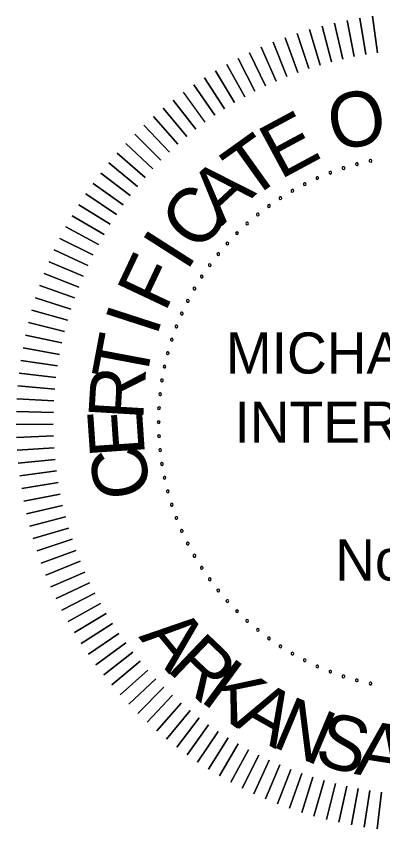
# Model space of a CAD drawing. Extents: x -4306 to 3843, y 131 to 8341.
# Drawn here: x 2723.6 to 2834.9, y 323.4 to 570.4 of the extents above; entities that cross this region are included whole.
import ezdxf

# ---------------------------------------------------------------- set-up
doc = ezdxf.new("R2010")
doc.units = 0
doc.layers.add('47', color=7, linetype='Continuous')

msp = doc.modelspace()

# ---------------------------------------------------------------- linework, layer by layer
at = {"layer": '47'}
for points in [[(2822.74, 557.35), (2820.23, 568.28)], [(2820.23, 568.28), (2822.74, 557.35)], [(2826.22, 558.09), (2824.06, 569.1)], [(2824.06, 569.1), (2826.22, 558.09)], [(2829.72, 558.72), (2827.9, 569.79)], [(2827.9, 569.79), (2829.72, 558.72)], [(2833.24, 559.24), (2831.77, 570.36)], [(2831.77, 570.36), (2833.24, 559.24)], [(2815.86, 555.54), (2812.67, 566.3)], [(2812.67, 566.3), (2815.86, 555.54)], [(2819.29, 556.5), (2816.44, 567.35)], [(2816.44, 567.35), (2819.29, 556.5)], [(2809.11, 553.3), (2805.25, 563.84)], [(2805.25, 563.84), (2809.11, 553.3)], [(2812.47, 554.47), (2808.94, 565.13)], [(2808.94, 565.13), (2812.47, 554.47)], [(2802.51, 550.65), (2798, 560.92)], [(2798, 560.92), (2802.51, 550.65)], [(2805.79, 552.03), (2801.6, 562.44)], [(2801.6, 562.44), (2805.79, 552.03)], [(2799.28, 549.17), (2794.44, 559.29)], [(2794.44, 559.29), (2799.28, 549.17)], [(2792.96, 545.9), (2787.5, 555.71)], [(2787.5, 555.71), (2792.96, 545.9)], [(2796.09, 547.58), (2790.94, 557.55)], [(2790.94, 557.55), (2796.09, 547.58)], [(2789.88, 544.12), (2784.11, 553.75)], [(2784.11, 553.75), (2789.88, 544.12)], [(2786.86, 542.25), (2780.79, 551.69)], [(2780.79, 551.69), (2786.86, 542.25)], [(2783.9, 540.28), (2777.54, 549.52)], [(2777.54, 549.52), (2783.9, 540.28)], [(2781, 538.22), (2774.35, 547.26)], [(2778.17, 536.07), (2771.24, 544.89)], [(2771.24, 544.89), (2778.17, 536.07)], [(2775.4, 533.83), (2768.2, 542.43)], [(2768.2, 542.43), (2775.4, 533.83)], [(2772.71, 531.5), (2765.24, 539.88)], [(2765.24, 539.88), (2772.71, 531.5)], [(2770.09, 529.09), (2762.37, 537.23)], [(2762.37, 537.23), (2770.09, 529.09)], [(2767.55, 526.6), (2759.57, 534.49)], [(2759.57, 534.49), (2767.55, 526.6)], [(2765.09, 524.04), (2756.87, 531.67)], [(2756.87, 531.67), (2765.09, 524.04)], [(2762.71, 521.39), (2754.25, 528.77)], [(2754.25, 528.77), (2762.71, 521.39)], [(2760.42, 518.67), (2751.73, 525.78)], [(2751.73, 525.78), (2760.42, 518.67)], [(2758.21, 515.89), (2749.3, 522.72)], [(2749.3, 522.72), (2758.21, 515.89)], [(2756.09, 513.03), (2746.97, 519.58)], [(2746.97, 519.58), (2756.09, 513.03)], [(2754.06, 510.11), (2744.74, 516.37)], [(2744.74, 516.37), (2754.06, 510.11)], [(2752.13, 507.13), (2742.62, 513.09)], [(2742.62, 513.09), (2752.13, 507.13)], [(2750.28, 504.08), (2740.59, 509.74)], [(2740.59, 509.74), (2750.28, 504.08)], [(2748.54, 500.98), (2738.67, 506.33)], [(2738.67, 506.33), (2748.54, 500.98)], [(2746.89, 497.83), (2736.86, 502.87)], [(2736.86, 502.87), (2746.89, 497.83)], [(2745.35, 494.63), (2735.16, 499.35)], [(2735.16, 499.35), (2745.35, 494.63)], [(2743.9, 491.38), (2733.58, 495.78)], [(2733.58, 495.78), (2743.9, 491.38)], [(2742.56, 488.08), (2732.1, 492.16)], [(2732.1, 492.16), (2742.56, 488.08)], [(2741.32, 484.75), (2730.74, 488.49)], [(2730.74, 488.49), (2741.32, 484.75)], [(2740.18, 481.38), (2729.49, 484.79)], [(2729.49, 484.79), (2740.18, 481.38)], [(2739.16, 477.97), (2728.36, 481.04)], [(2728.36, 481.04), (2739.16, 477.97)], [(2738.24, 474.54), (2727.35, 477.27)], [(2727.35, 477.27), (2738.24, 474.54)], [(2737.43, 471.08), (2726.46, 473.46)], [(2726.46, 473.46), (2737.43, 471.08)], [(2736.73, 467.59), (2725.69, 469.63)], [(2725.69, 469.63), (2736.73, 467.59)], [(2736.13, 464.08), (2725.04, 465.78)], [(2725.04, 465.78), (2736.13, 464.08)], [(2735.65, 460.56), (2724.51, 461.9)], [(2724.51, 461.9), (2735.65, 460.56)], [(2735.28, 457.02), (2724.1, 458.01)], [(2724.1, 458.01), (2735.28, 457.02)], [(2735.02, 453.47), (2723.82, 454.11)], [(2723.82, 454.11), (2735.02, 453.47)], [(2734.87, 449.92), (2723.66, 450.21)], [(2723.66, 450.21), (2734.87, 449.92)], [(2734.84, 446.36), (2723.62, 446.3)], [(2723.62, 446.3), (2734.84, 446.36)], [(2734.91, 442.81), (2723.7, 442.39)], [(2723.7, 442.39), (2734.91, 442.81)], [(2735.1, 439.25), (2723.91, 438.49)], [(2723.91, 438.49), (2735.1, 439.25)], [(2735.4, 435.71), (2724.23, 434.59)], [(2724.23, 434.59), (2735.4, 435.71)], [(2735.81, 432.18), (2724.68, 430.71)], [(2724.68, 430.71), (2735.81, 432.18)], [(2736.33, 428.66), (2725.26, 426.84)], [(2725.26, 426.84), (2736.33, 428.66)], [(2736.96, 425.16), (2725.95, 422.99)], [(2725.95, 422.99), (2736.96, 425.16)], [(2737.7, 421.68), (2726.76, 419.17)], [(2726.76, 419.17), (2737.7, 421.68)], [(2738.55, 418.23), (2727.7, 415.37)], [(2727.7, 415.37), (2738.55, 418.23)], [(2739.51, 414.8), (2728.75, 411.61)], [(2728.75, 411.61), (2739.51, 414.8)], [(2740.57, 411.41), (2729.92, 407.88)], [(2729.92, 407.88), (2740.57, 411.41)], [(2741.75, 408.05), (2731.21, 404.19)], [(2731.21, 404.19), (2741.75, 408.05)], [(2743.02, 404.73), (2732.61, 400.54)], [(2732.61, 400.54), (2743.02, 404.73)], [(2744.4, 401.45), (2734.13, 396.94)], [(2734.13, 396.94), (2744.4, 401.45)], [(2745.88, 398.22), (2735.75, 393.38)], [(2735.75, 393.38), (2745.88, 398.22)], [(2747.46, 395.03), (2737.49, 389.88)], [(2737.49, 389.88), (2747.46, 395.03)], [(2749.15, 391.9), (2739.34, 386.44)], [(2739.34, 386.44), (2749.15, 391.9)], [(2750.93, 388.82), (2741.3, 383.05)], [(2741.3, 383.05), (2750.93, 388.82)], [(2752.8, 385.8), (2743.36, 379.73)], [(2743.36, 379.73), (2752.8, 385.8)], [(2754.77, 382.83), (2745.52, 376.47)], [(2745.52, 376.47), (2754.77, 382.83)], [(2756.83, 379.94), (2747.79, 373.29)], [(2747.79, 373.29), (2756.83, 379.94)], [(2758.98, 377.1), (2750.15, 370.18)], [(2750.15, 370.18), (2758.98, 377.1)], [(2761.22, 374.34), (2752.62, 367.14)], [(2752.62, 367.14), (2761.22, 374.34)], [(2763.55, 371.65), (2755.17, 364.18)], [(2755.17, 364.18), (2763.55, 371.65)], [(2765.96, 369.03), (2757.82, 361.3)], [(2757.82, 361.3), (2765.96, 369.03)], [(2768.45, 366.49), (2760.55, 358.51)], [(2760.55, 358.51), (2768.45, 366.49)], [(2771.01, 364.03), (2763.38, 355.81)], [(2763.38, 355.81), (2771.01, 364.03)], [(2766.28, 353.19), (2773.66, 361.65)], [(2773.66, 361.65), (2766.28, 353.19)], [(2769.27, 350.67), (2776.37, 359.36)], [(2776.37, 359.36), (2769.27, 350.67)], [(2772.33, 348.24), (2779.16, 357.15)], [(2779.16, 357.15), (2772.33, 348.24)], [(2775.47, 345.91), (2782.02, 355.03)], [(2782.02, 355.03), (2775.47, 345.91)], [(2778.68, 343.68), (2784.94, 353)], [(2784.94, 353), (2778.68, 343.68)], [(2781.96, 341.55), (2787.92, 351.06)], [(2787.92, 351.06), (2781.96, 341.55)], [(2785.31, 339.53), (2790.97, 349.22)], [(2790.97, 349.22), (2785.31, 339.53)], [(2788.71, 337.61), (2794.07, 347.48)], [(2794.07, 347.48), (2788.71, 337.61)], [(2792.18, 335.8), (2797.22, 345.83)], [(2797.22, 345.83), (2792.18, 335.8)], [(2795.7, 334.1), (2800.42, 344.28)], [(2800.42, 344.28), (2795.7, 334.1)], [(2799.27, 332.51), (2803.67, 342.84)], [(2803.67, 342.84), (2799.27, 332.51)], [(2802.89, 331.04), (2806.96, 341.49)], [(2806.96, 341.49), (2802.89, 331.04)], [(2806.56, 329.68), (2810.3, 340.26)], [(2810.3, 340.26), (2806.56, 329.68)], [(2810.26, 328.43), (2813.67, 339.12)], [(2813.67, 339.12), (2810.26, 328.43)], [(2814, 327.3), (2817.07, 338.1)], [(2817.07, 338.1), (2814, 327.3)], [(2817.78, 326.29), (2820.51, 337.18)], [(2820.51, 337.18), (2817.78, 326.29)], [(2821.59, 325.4), (2823.97, 336.37)], [(2823.97, 336.37), (2821.59, 325.4)], [(2825.42, 324.63), (2827.46, 335.66)], [(2827.46, 335.66), (2825.42, 324.63)], [(2829.27, 323.98), (2830.97, 335.07)], [(2830.97, 335.07), (2829.27, 323.98)], [(2833.15, 323.45), (2834.49, 334.59)], [(2834.49, 334.59), (2833.15, 323.45)]]:
    msp.add_lwpolyline(points, dxfattribs=at)
for centre, start, end in [((2831.17, 526.43), 12, 192), ((2831.17, 526.43), 192, 12), ((2822.96, 524.23), 18, 198), ((2822.96, 524.23), 198, 18), ((2827.04, 525.44), 15, 195), ((2827.04, 525.44), 195, 15), ((2815.02, 521.19), 24, 204), ((2815.02, 521.19), 204, 24), ((2818.95, 522.81), 21, 201), ((2818.95, 522.81), 201, 21), ((2811.18, 519.36), 27, 207), ((2811.18, 519.36), 207, 27), ((2807.45, 517.33), 30, 210), ((2807.45, 517.33), 210, 30), ((2803.82, 515.11), 33, 213), ((2803.82, 515.11), 213, 33), ((2800.32, 512.7), 36, 216), ((2800.32, 512.7), 216, 36), ((2796.95, 510.11), 39, 219), ((2796.95, 510.11), 219, 39), ((2793.71, 507.35), 42, 222), ((2793.71, 507.35), 222, 42), ((2790.63, 504.42), 45, 225), ((2790.63, 504.42), 225, 45), ((2787.7, 501.34), 48, 228), ((2787.7, 501.34), 228, 48), ((2784.94, 498.1), 51, 231), ((2784.94, 498.1), 231, 51), ((2782.35, 494.73), 54, 234), ((2782.35, 494.73), 234, 54), ((2779.94, 491.23), 57, 237), ((2779.94, 491.23), 237, 57), ((2777.72, 487.6), 60, 240), ((2777.72, 487.6), 240, 60), ((2775.69, 483.86), 63, 243), ((2775.69, 483.86), 243, 63), ((2773.86, 480.03), 66, 246), ((2773.86, 480.03), 246, 66), ((2772.23, 476.1), 69, 249), ((2772.23, 476.1), 249, 69), ((2770.82, 472.09), 72, 252), ((2770.82, 472.09), 252, 72), ((2769.61, 468.01), 75, 255), ((2769.61, 468.01), 255, 75), ((2768.62, 463.88), 78, 258), ((2768.62, 463.88), 258, 78), ((2767.84, 459.7), 81, 261), ((2767.84, 459.7), 261, 81), ((2767.29, 455.48), 84, 264), ((2767.29, 455.48), 264, 84), ((2766.95, 451.24), 87, 267), ((2766.95, 451.24), 267, 87), ((2766.84, 446.99), 90, 270), ((2766.84, 446.99), 270, 90), ((2766.95, 442.74), 93, 273), ((2766.95, 442.74), 273, 93), ((2767.29, 438.5), 96, 276), ((2767.29, 438.5), 276, 96), ((2767.84, 434.29), 99, 279), ((2767.84, 434.29), 279, 99), ((2768.62, 430.11), 102, 282), ((2768.62, 430.11), 282, 102), ((2769.61, 425.97), 105, 285), ((2769.61, 425.97), 285, 105), ((2770.82, 421.9), 108, 288), ((2770.82, 421.9), 288, 108), ((2772.23, 417.89), 111, 291), ((2772.23, 417.89), 291, 111), ((2773.86, 413.96), 114, 294), ((2773.86, 413.96), 294, 114), ((2775.69, 410.12), 117, 297), ((2775.69, 410.12), 297, 117), ((2777.72, 406.39), 120, 300), ((2777.72, 406.39), 300, 120), ((2779.94, 402.76), 123, 303), ((2779.94, 402.76), 303, 123), ((2782.35, 399.26), 126, 306), ((2782.35, 399.26), 306, 126), ((2784.94, 395.88), 129, 309), ((2784.94, 395.88), 309, 129), ((2787.7, 392.65), 132, 312), ((2787.7, 392.65), 312, 132), ((2790.63, 389.57), 135, 315), ((2790.63, 389.57), 315, 135), ((2793.71, 386.64), 138, 318), ((2793.71, 386.64), 318, 138), ((2796.95, 383.88), 141, 321), ((2796.95, 383.88), 321, 141), ((2800.32, 381.29), 144, 324), ((2800.32, 381.29), 324, 144), ((2803.82, 378.88), 147, 327), ((2803.82, 378.88), 327, 147), ((2807.45, 376.66), 150, 330), ((2807.45, 376.66), 330, 150), ((2811.18, 374.63), 153, 333), ((2811.18, 374.63), 333, 153), ((2815.02, 372.8), 156, 336), ((2815.02, 372.8), 336, 156), ((2818.95, 371.17), 159, 339), ((2818.95, 371.17), 339, 159), ((2822.96, 369.75), 162, 342), ((2822.96, 369.75), 342, 162), ((2827.04, 368.55), 165, 345), ((2827.04, 368.55), 345, 165), ((2831.17, 367.55), 348, 168), ((2831.17, 367.55), 168, 348)]:
    msp.add_arc(centre, 0.417, start, end, dxfattribs=at)

# ---------------------------------------------------------------- texts
for s, rotation, p in [('O', 10.7295, (2819.9, 529.32)), ('E', 28.279, (2803.71, 520.59)), ('T', 35.5725, (2794.41, 514.13)), ('A', 42.8659, (2785.94, 506.43)), ('C', 50.1594, (2778.93, 498.1)), ('I', 57.4529, (2775.31, 492.53)), ('F', 64.7464, (2768.77, 480.07)), ('I', 72.0398, (2766.19, 472.74)), ('T', 79.3333, (2762.87, 458.38)), ('R', 86.6268, (2762.11, 447.36)), ('E', 93.9203, (2762.72, 436.95)), ('C', 101.2137, (2764.86, 425.36)), ('A', 309.5859, (2760.59, 381.73)), ('R', 316.3356, (2768.87, 371.9)), ('K', 323.6428, (2779.06, 362.44)), ('A', 330.3925, (2789.48, 354.92)), ('N', 337.1422, (2800.71, 348.67)), ('S', 344.4494, (2813.6, 343.45)), ('A', 351.1991, (2826, 340.11))]:
    msp.add_text(s, height=16.67, rotation=rotation, dxfattribs=at).set_placement(p)
for s, height, p in [('MICHAEL BAKER', 12.5016, (2787.23, 461.77)), (' INTERNATIONAL', 12.5016, (2785.22, 440.75)), (' No. 1126', 12.502, (2815.79, 398.89))]:
    msp.add_text(s, height=height, dxfattribs=at).set_placement(p)

doc.saveas('drawing.dxf')
